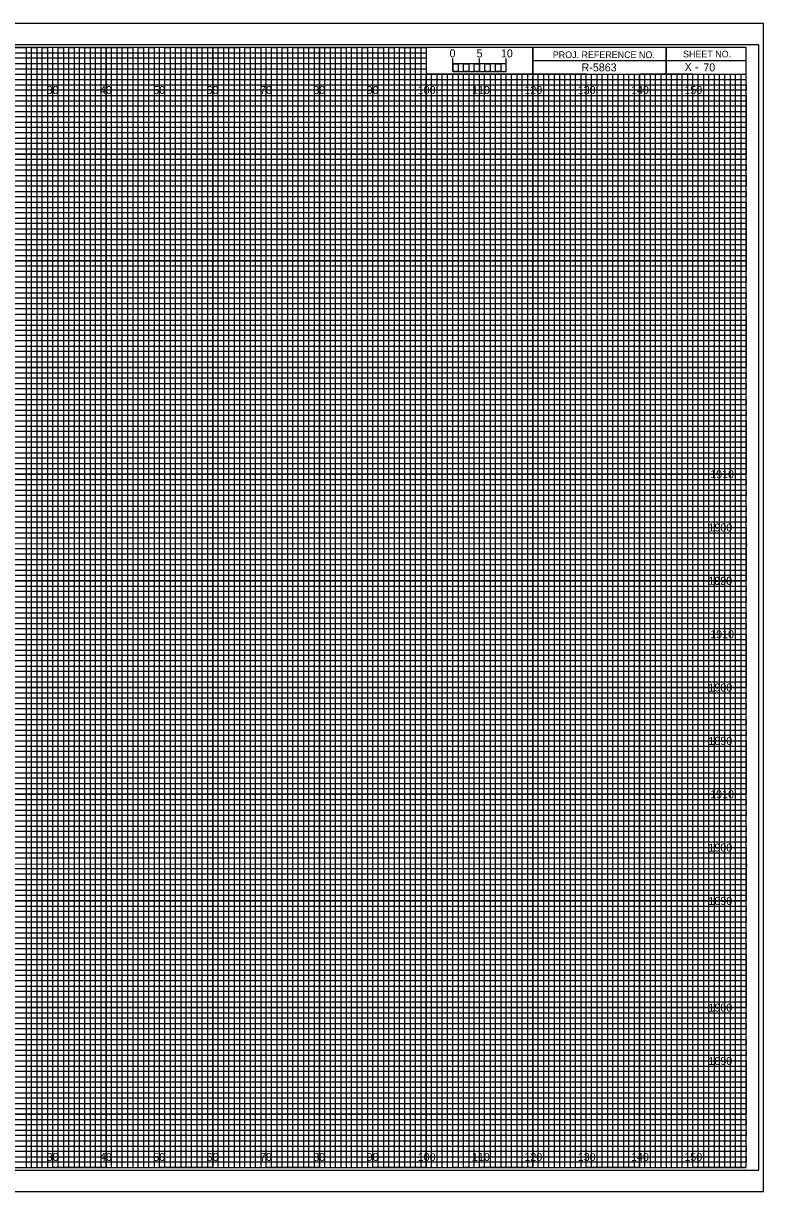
# Model space of a CAD drawing. Extents: x -13 to 323, y -4 to 214.
# Drawn here: x 184.5 to 323.3, y -4.5 to 214.5 of the extents above; entities that cross this region are included whole.
import ezdxf

# ---------------------------------------------------------------- set-up
doc = ezdxf.new("R2010")
doc.units = 0
for name, color, linetype in [('Prop XS Bar Scale Labels', 7, 'Continuous'), ('Prop XS Elevation Labels', 7, 'Continuous'), ('Prop XS Offset Labels', 7, 'Continuous'), ('Prop XS Project Number', 7, 'Continuous'), ('Prop XS Sheet Number', 7, 'Continuous'), ('Sheet Cross Section CELL', 7, 'Continuous'), ('Sheet Cross Section Grid Major CELL', 7, 'Continuous'), ('Sheet Cross Section Grid Middle CELL', 7, 'Continuous'), ('Sheet Cross Section Grid Minor 1 CELL', 7, 'Continuous'), ('Sheet Cross Section Grid Minor 2 CELL', 7, 'Continuous'), ('Sheet Cross Section Scale CELL', 7, 'Continuous'), ('Sheet Cutting Line CELL', 7, 'Continuous'), ('Sheet DOT Grid CELL', 7, 'Continuous'), ('Sheet Plot Border Inside CELL', 7, 'Continuous'), ('Sheet Plot Border Outside CELL', 7, 'Continuous')]:
    doc.layers.add(name, color=color, linetype=linetype)

msp = doc.modelspace()

# ---------------------------------------------------------------- linework, layer by layer
at = {"layer": 'Sheet Cross Section CELL'}
for p, q in [((305, 210), (305, 205)), ((305, 205), (305, 210)), ((280, 207.5), (280, 205)), ((320, 207.49), (280, 207.49)), ((280, 205), (320, 205))]:
    msp.add_line(p, q, dxfattribs=at)
for points in [[(320, 210), (0, 210), (0, 0), (320, 0)], [(280, 210), (260, 210), (260, 205.03), (280, 205.03)], [(320, 210), (280, 210), (280, 205), (320, 205)]]:
    msp.add_lwpolyline(points, close=True, dxfattribs=at)
at = {"layer": 'Sheet Cross Section Grid Major CELL'}
for p, q in [((190, 210), (180, 210)), ((190, 0), (190, 210)), ((210, 210), (200, 210)), ((200, 210), (200, 0)), ((210, 0), (210, 210)), ((230, 210), (220, 210)), ((220, 210), (220, 0)), ((230, 0), (230, 210)), ((250, 210), (240, 210)), ((240, 210), (240, 0)), ((250, 0), (250, 210)), ((260, 210), (260, 0)), ((270, 0), (270, 205)), ((290, 205), (280, 205)), ((280, 205), (280, 0)), ((290, 0), (290, 205)), ((310, 205), (300, 205)), ((300, 205), (300, 0)), ((310, 0), (310, 205)), ((200, 0), (190, 0)), ((220, 0), (210, 0)), ((240, 0), (230, 0)), ((260, 0), (250, 0)), ((280, 0), (270, 0)), ((300, 0), (290, 0)), ((320, 0), (310, 0)), ((320, 0), (320, 0))]:
    msp.add_line(p, q, dxfattribs=at)
for points in [[(0, 200), (320, 200), (320, 190), (0, 190)], [(0, 180), (320, 180), (320, 170), (0, 170)], [(0, 160), (320, 160), (320, 150), (0, 150)], [(0, 140), (320, 140), (320, 130), (0, 130)], [(0, 120), (320, 120), (320, 110), (0, 110)], [(0, 100), (320, 100), (320, 90), (0, 90)], [(0, 80), (320, 80), (320, 70), (0, 70)], [(0, 60), (320, 60), (320, 50), (0, 50)], [(0, 40), (320, 40), (320, 30), (0, 30)], [(0, 20), (320, 20), (320, 10), (0, 10)]]:
    msp.add_lwpolyline(points, dxfattribs=at)
at = {"layer": 'Sheet Cross Section Grid Middle CELL'}
for points in [[(175, 210), (185, 210), (185, 0), (195, 0), (195, 210), (205, 210), (205, 0), (215, 0), (215, 210), (225, 210), (225, 0), (235, 0), (235, 210), (245, 210), (245, 0), (255, 0), (255, 210), (259.93, 210), (260, 210), (260, 205), (264.99, 205), (264.99, 0), (275, 0), (275, 205), (285, 205), (285, 0), (295, 0), (295, 205), (305, 205), (305, 0), (315, 0), (315, 205)], [(0, 205), (275, 205)], [(0, 185), (320, 185), (320, 195), (0, 195)], [(0, 165), (320, 165), (320, 175), (0, 175)], [(0, 145), (320, 145), (320, 155), (0, 155)], [(0, 125), (320, 125), (320, 135), (0, 135)], [(0, 105), (320, 105), (320, 115), (0, 115)], [(0, 85), (320, 85), (320, 95), (0, 95)], [(0, 65), (320, 65), (320, 75), (0, 75)], [(0, 45), (320, 45), (320, 55), (0, 55)], [(0, 25), (320, 25), (320, 35), (0, 35)], [(0, 5), (320, 5), (320, 15), (0, 15)]]:
    msp.add_lwpolyline(points, dxfattribs=at)
at = {"layer": 'Sheet Cross Section Grid Minor 1 CELL'}
for p, q in [((0, 209), (260, 209)), ((260, 209), (260, 207.98)), ((260, 207.98), (0, 207.98)), ((0, 207), (260, 207)), ((260, 205.89), (0, 205.89)), ((260, 207), (260, 205.89)), ((0, 204), (320, 204))]:
    msp.add_line(p, q, dxfattribs=at)
for points in [[(0, 203), (270, 203), (320, 203), (320, 202), (0, 202)], [(0, 201), (320, 201), (320, 199), (0, 199)], [(0, 198), (320, 198), (320, 197), (0, 196.98)], [(0, 196), (320, 196), (320, 194), (0, 194)], [(0, 193), (320, 193), (320, 192), (0, 192)], [(0, 191), (320, 191), (320, 189), (0, 189)], [(0, 188), (320, 188), (320, 187), (0, 187)], [(0, 186), (320, 186), (320, 184), (0, 184)], [(0, 183), (320, 183), (320, 182), (0, 182)], [(0, 181), (320, 181), (320, 179), (0, 179)], [(0, 178), (320, 178), (320, 177), (0, 177)], [(0, 176), (320, 176), (320, 173.95), (320, 173), (320, 172), (0, 172)], [(0, 174), (320, 174), (320, 173), (0, 173)], [(0, 171), (320, 171), (320, 169), (0, 169.03)], [(0, 169.03), (320, 169), (320, 168), (0, 168)], [(0, 167), (320, 167), (320, 166), (0, 166)], [(0, 164), (320, 164), (320, 163), (0, 163)], [(0, 162), (320, 162), (320, 161), (0, 161)], [(-0.07, 158.89), (320, 158.89), (320, 157.88), (-0.07, 157.88)], [(0, 157), (320, 157), (320, 156), (0, 156)], [(0, 154), (320, 154), (320, 153), (0, 153)], [(0, 152), (320, 152), (320, 151), (0, 151)], [(0, 149), (320, 149), (320, 148), (0, 148)], [(0, 147), (320, 147), (320, 146), (0, 146)], [(0, 144), (320, 144), (320, 143), (0, 143)], [(0, 142), (320, 142), (320, 141), (0, 141)], [(0, 139), (320, 139), (319.99, 137.98), (0, 138)], [(0, 137), (320, 137), (320, 136), (0, 136)], [(0, 134), (320, 134), (320, 133), (0, 133)], [(0, 132), (320, 132), (320, 131), (0, 131)], [(0, 129), (320, 129), (320, 128), (0, 128)], [(0, 127), (320, 127), (320, 126), (0, 126)], [(0, 124), (320, 124), (320, 123), (0, 123)], [(0, 122), (320, 122), (320, 121), (0, 121)], [(0, 119), (320, 119), (320, 118), (0, 118)], [(0, 116.99), (320.07, 116.91), (320, 116), (0, 116)], [(0, 114), (320, 114), (320, 113), (0, 113)], [(0, 112), (320, 112), (320, 111), (0, 111)], [(0, 109), (320, 109), (320, 108), (0, 108)], [(0, 107), (320, 107), (320, 106), (0, 106)], [(0, 104), (320, 104), (320, 103), (0, 103)], [(0, 102), (320, 102), (320, 101), (0, 101)], [(0, 99), (320, 99), (320, 98), (0, 98)], [(0, 97), (320, 97), (320, 96), (0, 96)], [(0, 94), (320, 94), (320, 93), (0, 93)], [(0, 92), (320, 92), (320, 91), (0, 91)], [(0, 89), (320, 89), (320, 88), (0, 88)], [(0, 87), (320, 87), (320, 86), (0, 86)], [(0, 84), (320, 84), (320, 83), (0, 83)], [(0, 82), (320, 82), (320, 81), (0, 81)], [(0, 79), (320, 79), (319.99, 77.98), (0, 78)], [(0, 77), (320, 77), (320, 76), (0, 76)], [(0, 74), (320, 74), (320, 73), (0, 73)], [(0, 72), (320, 72), (320, 71), (0, 71)], [(0, 69), (320, 69), (320, 68), (0, 68)], [(0, 67), (320, 67), (320, 66), (0, 66)], [(0, 64), (320, 64), (320, 63), (0, 63)], [(0, 62), (320, 62), (320, 61), (0, 61)], [(0, 59), (320, 59), (320, 58), (0, 58)], [(0, 56.99), (320.07, 56.91), (320, 56), (0, 56)], [(0, 54), (320, 54), (320, 53), (0, 53)], [(0, 52), (320, 52), (320, 51), (0, 51)], [(0, 49), (320, 49), (320, 48), (0, 48)], [(0, 47), (320, 47), (320, 46), (0, 46)], [(0, 44), (320, 44), (320, 43), (0, 43)], [(0, 42), (320, 42), (320, 41), (0, 41)], [(0, 39), (320, 39), (320, 38), (0, 38)], [(0, 37), (320, 37), (320, 36), (0, 36)], [(0, 34), (320, 34), (320, 33), (0, 33)], [(0, 32), (320, 32), (320, 31), (0, 31)], [(0, 29), (320, 29), (320, 28), (0, 28)], [(0, 27), (320, 27), (320, 26), (0, 26)], [(0, 24), (320, 24), (320, 23), (0, 23)], [(0, 22), (320, 22), (320, 21), (0, 21)], [(0, 19), (320, 19), (320, 18), (0, 18)], [(0, 17), (320, 17), (320, 16), (0, 16)], [(0, 14), (320, 14), (320, 13), (0, 13)], [(0, 12), (320, 12), (320, 11), (0, 11)], [(0, 9), (320, 9), (320, 8), (0, 8)], [(0, 7), (320, 7), (320, 6), (0, 6)], [(0, 4), (320, 4), (320, 3), (0, 3)], [(0, 2), (320, 2), (320, 1), (0, 1)]]:
    msp.add_lwpolyline(points, dxfattribs=at)
at = {"layer": 'Sheet Cross Section Grid Minor 2 CELL'}
for p, q in [((267, 205), (266.01, 205)), ((266.01, 205), (266.01, 0)), ((267, 0), (267, 205)), ((269, 205), (268, 205)), ((268, 205), (268, 0)), ((269, 0), (269, 205)), ((266.01, 0), (265, 0)), ((268, 0), (267, 0))]:
    msp.add_line(p, q, dxfattribs=at)
for points in [[(185, 0), (186, 0), (186, 210), (187, 210), (187, 0)], [(187, 0), (188, 0), (188, 210), (189, 210), (189, 0)], [(190, 0), (191, 0), (191, 210), (192, 210), (192, 0)], [(192, 0), (193, 0), (193, 210), (194, 210), (194, 0)], [(195, 0), (196, 0), (196, 210), (197, 210), (197, 0)], [(197, 0), (198, 0), (198, 210), (199, 210), (199, 0)], [(200, 0), (201, 0), (201, 210), (202, 210), (202, 0)], [(202, 0), (203, 0), (203, 210), (204, 210), (204, 0)], [(205, 0), (206, 0), (206, 210), (207, 210), (207, 0)], [(207, 0), (208, 0), (208, 210), (209, 210), (209, 0)], [(210, 0), (211, 0), (211, 210), (212, 210), (212, 0)], [(212, 0), (213, 0), (213, 210), (214, 210), (214, 0)], [(215, 0), (216, 0), (216, 210), (217, 210), (217, 0)], [(217, 0), (218, 0), (218, 210), (219, 210), (219, 0)], [(220, 0), (221, 0), (221, 210), (222, 210), (222, 0)], [(222, 0), (223, 0), (223, 210), (224, 210), (224, 0)], [(225, 0), (226, 0), (226, 210), (227, 210), (227, 0)], [(227, 0), (228, 0), (228, 210), (229, 210), (229, 0)], [(230, 0), (231, 0), (231, 210), (232, 210), (232, 0)], [(232, 0), (233, 0), (233, 210), (234, 210), (234, 0)], [(235, 0), (236, 0), (236, 210), (237, 210), (237, 0)], [(237, 0), (238, 0), (238, 210), (239, 210), (239, 0)], [(240, 0), (241, 0), (241, 210), (242, 210), (242, 0)], [(242, 0), (243, 0), (243, 210), (244, 210), (244, 0)], [(245, 0), (246, 0), (246, 210), (247, 210), (247, 0)], [(247, 0), (248, 0), (248, 210), (249, 210), (249, 0)], [(250, 0), (251, 0), (251, 210), (252, 210), (252, 0)], [(252, 0), (253, 0), (253, 210), (254, 210), (254, 0)], [(255, 0), (256, 0), (256, 210), (257, 210), (257, 0)], [(257, 0), (258, 0), (258, 210), (259, 210), (259, 0)], [(260, 0), (261, 0), (261, 205), (262.02, 205), (262.02, 0)], [(262, 0), (263, 0), (263, 205), (263.99, 205), (263.99, 0)], [(270, 0), (270.98, 0), (270.98, 205), (272, 205), (272, 0)], [(272, 0), (273, 0), (273, 205), (274.05, 205), (274.05, 0)], [(275, 0), (276, 0), (276, 205), (277, 205), (277, 0)], [(277, 0), (278, 0), (278, 205), (279, 205), (279, 0)], [(280, 0), (281, 0), (281, 205), (282, 205), (282, 0)], [(282, 0), (283, 0), (283, 205), (284, 205), (284, 0)], [(285, 0), (286, 0), (286, 205), (287, 205), (287, 0)], [(287, 0), (288, 0), (288, 205), (289, 205), (289, 0)], [(290, 0), (291, 0), (291, 205), (292, 205), (292, 0)], [(292, 0), (293, 0), (293, 205), (294, 205), (294, 0)], [(295, 0), (296, 0), (296, 205), (297, 205), (297, 0)], [(297, 0), (298, 0), (298, 205), (299, 205), (299, 0)], [(300, 0), (301, 0), (301, 205), (302, 205), (302, 0)], [(302, 0), (303, 0), (303, 205), (304, 205), (304, 0)], [(305, 0), (306, 0), (306, 205), (307, 205), (307, 0)], [(307, 0), (308, 0), (308, 205), (309, 205), (309, 0)], [(310, 0), (311, 0), (311, 205), (312, 205), (312, 0)], [(312, 0), (313, 0), (313, 205), (314, 205), (314, 0)], [(315, 0), (316, 0), (316, 205), (317, 205), (317, 0)], [(317, 0), (318, 0), (318, 205), (319, 205), (319, 0)]]:
    msp.add_lwpolyline(points, dxfattribs=at)
at = {"layer": 'Sheet Cross Section Scale CELL'}
for p, q in [((265, 205.49), (265, 207.9)), ((265, 206.9), (265, 207.9)), ((270, 205.49), (270, 207.9)), ((275, 205.49), (275, 207.9)), ((275, 206.9), (275, 207.9))]:
    msp.add_line(p, q, dxfattribs=at)
for points in [[(275, 206.9), (265, 206.9), (265, 205.49), (275, 205.49)], [(265, 206.9), (266, 206.9), (266, 205.49), (265, 205.49)], [(267, 206.9), (268, 206.9), (268, 205.49), (267, 205.49)], [(269, 206.9), (270, 206.9), (270, 205.49), (269, 205.49)], [(271, 206.9), (272, 206.9), (272, 205.49), (271, 205.49)], [(273, 206.9), (274, 206.9), (274, 205.49), (273, 205.49)]]:
    msp.add_lwpolyline(points, close=True, dxfattribs=at)
at = {"layer": 'Sheet Cutting Line CELL'}
for p, q in [((323.3, 214.5), (-13.4, 214.5)), ((-13.4, -4.5), (323.3, -4.5))]:
    msp.add_line(p, q, dxfattribs=at)
at = {"layer": 'Sheet DOT Grid CELL'}
for p, q in [((190, 0), (190, 210)), ((200, 0), (200, 210)), ((210, 0), (210, 210)), ((220, 0), (220, 210)), ((230, 0), (230, 210)), ((240, 0), (240, 210)), ((250, 0), (250, 210)), ((260, 0), (260, 204.69)), ((270, 0), (270, 204.69)), ((280, 0), (280, 204.69)), ((290, 0), (290, 204.69)), ((300, 0), (300, 204.69)), ((310, 0), (310, 204.69)), ((0, 200), (320, 200)), ((0, 190), (320, 190)), ((0, 180), (320, 180)), ((0, 170), (320, 170)), ((0, 160), (320, 160)), ((0, 150), (320, 150)), ((0, 140), (320, 140)), ((0, 130), (320, 130)), ((0, 120), (320, 120)), ((0, 110), (320, 110)), ((0, 100), (320, 100)), ((0, 90), (320, 90)), ((0, 80), (320, 80)), ((0, 70), (320, 70)), ((0, 60), (320, 60)), ((0, 50), (320, 50)), ((0, 40), (320, 40)), ((0, 30), (320, 30)), ((0, 20), (320, 20)), ((0, 10), (320, 10))]:
    msp.add_line(p, q, dxfattribs=at)
at = {"layer": 'Sheet Plot Border Inside CELL'}
msp.add_lwpolyline([(-10.8, -0.5), (322.4, -0.5), (322.4, 210.5), (-10.8, 210.5)], close=True, dxfattribs=at)
at = {"layer": 'Sheet Plot Border Outside CELL'}
msp.add_lwpolyline([(-13.4, -4.5), (323.3, -4.5), (323.3, 214.5), (-13.4, 214.5)], close=True, dxfattribs=at)

# ---------------------------------------------------------------- texts
at = {"layer": 'Prop XS Bar Scale Labels'}
for s, p in [('5', (269.47, 208.12)), ('10', (274.04, 208.12))]:
    msp.add_text(s, height=1.5, dxfattribs=at).set_placement(p)
at = {"layer": 'Prop XS Elevation Labels'}
for s, p in [('1910', (313.28, 129.25)), ('1900', (312.95, 119.25)), ('1920', (312.9, 109.25)), ('1890', (312.95, 109.25)), ('1910', (313.28, 99.25)), ('1900', (312.95, 89.25)), ('1890', (312.95, 79.25)), ('1910', (313.28, 69.25)), ('1900', (312.95, 59.25)), ('1890', (312.95, 49.25)), ('1900', (312.95, 29.25)), ('1890', (312.95, 19.25))]:
    msp.add_text(s, height=1.5, dxfattribs=at).set_placement(p)
at = {"layer": 'Prop XS Offset Labels'}
for s, p in [('30', (188.86, 201.25)), ('40', (198.86, 201.25)), ('50', (208.86, 201.25)), ('60', (218.86, 201.25)), ('70', (228.86, 201.25)), ('80', (238.86, 201.25)), ('90', (248.86, 201.25)), ('100', (258.44, 201.25)), ('110', (268.62, 201.25)), ('120', (278.44, 201.25)), ('130', (288.44, 201.25)), ('140', (298.44, 201.25)), ('150', (308.44, 201.25)), ('30', (188.86, 1.25)), ('40', (198.86, 1.25)), ('50', (208.86, 1.25)), ('60', (218.86, 1.25)), ('70', (228.86, 1.25)), ('80', (238.86, 1.25)), ('90', (248.86, 1.25)), ('100', (258.44, 1.25)), ('110', (268.62, 1.25)), ('120', (278.44, 1.25)), ('130', (288.44, 1.25)), ('140', (298.44, 1.25)), ('150', (308.44, 1.25))]:
    msp.add_text(s, height=1.5, dxfattribs=at).set_placement(p)
at = {"layer": 'Prop XS Project Number'}
msp.add_text('R-5863', height=1.5, dxfattribs=at).set_placement((289.16, 205.5))
at = {"layer": 'Prop XS Sheet Number'}
msp.add_text('70', height=1.5, dxfattribs=at).set_placement((311.99, 205.5))
at = {"layer": 'Sheet Cross Section CELL'}
for s, height, p in [('PROJ. REFERENCE NO.', 1.25, (283.77, 207.99)), ('SHEET NO.', 1.25, (308.19, 208.12)), ('X -    ', 1.5, (308.5, 205.58))]:
    msp.add_text(s, height=height, dxfattribs=at).set_placement(p)
at = {"layer": 'Sheet Cross Section Scale CELL'}
msp.add_text('0', height=1.5, dxfattribs=at).set_placement((264.41, 208.12))

doc.saveas('drawing.dxf')
